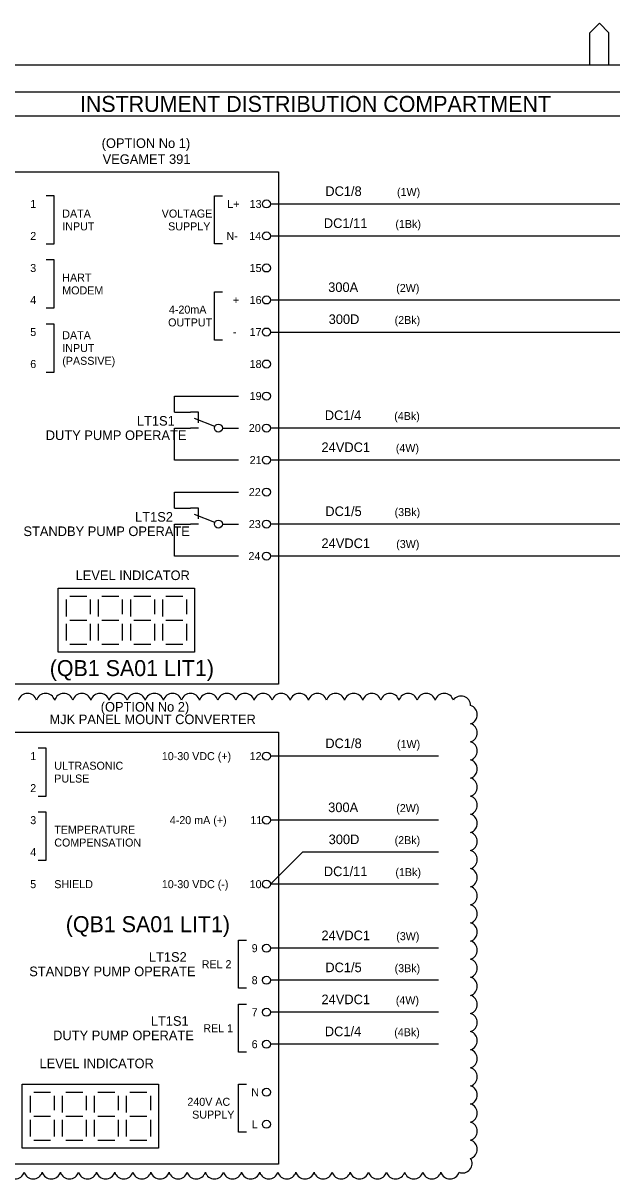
# Model space of a CAD drawing. Extents: x 0 to 841, y 0 to 594.
# Drawn here: x 240.3 to 424.1, y 232.9 to 594 of the extents above; entities that cross this region are included whole.
import ezdxf

# ---------------------------------------------------------------- set-up
doc = ezdxf.new("R2010")
doc.units = 0
for name, color, linetype in [('A1BORDER', 7, 'Continuous'), ('BASE', 7, 'Continuous'), ('Level 1', 7, 'Continuous'), ('Level 10', 7, 'Continuous'), ('Level 2', 7, 'Continuous')]:
    doc.layers.add(name, color=color, linetype=linetype)

msp = doc.modelspace()

# ---------------------------------------------------------------- linework, layer by layer
at = {"layer": 'A1BORDER'}
for p, q in [((417.19, 591), (420.19, 594)), ((423.19, 591), (420.19, 594)), ((417.19, 581), (417.19, 591)), ((423.19, 581), (423.19, 591)), ((28, 581), (829, 581))]:
    msp.add_line(p, q, dxfattribs=at)
at = {"layer": 'BASE'}
for p, q in [((317.5, 537.5), (602.5, 537.5)), ((317.5, 527.5), (602.5, 527.5)), ((317.5, 507.5), (602.5, 507.5)), ((317.5, 497.5), (602.5, 497.5))]:
    msp.add_line(p, q, dxfattribs=at)
at = {"layer": 'Level 1'}
for p, q in [((120, 572.5), (829, 572.5)), ((120, 565), (829, 565)), ((315, 537.5), (315, 537.5)), ((317.5, 537.5), (317.5, 537.5)), ((315, 527.5), (315, 527.5)), ((317.5, 527.5), (317.5, 527.5)), ((315, 517.5), (315, 517.5)), ((317.5, 517.5), (317.5, 517.5)), ((315, 507.5), (315, 507.5)), ((317.5, 507.5), (317.5, 507.5)), ((315, 497.5), (315, 497.5)), ((317.5, 497.5), (317.5, 497.5)), ((315, 487.5), (315, 487.5)), ((317.5, 487.5), (317.5, 487.5)), ((287.5, 472.5), (287.5, 477.5)), ((287.5, 477.5), (307.5, 477.5)), ((315, 477.5), (315, 477.5)), ((317.5, 477.5), (317.5, 477.5)), ((287.5, 472.5), (292.5, 472.5)), ((287.5, 457.5), (287.5, 467.5)), ((287.5, 467.5), (292.5, 467.5)), ((292.5, 467.5), (292.5, 467.5)), ((302.5, 467.5), (302.5, 467.5)), ((302.5, 467.5), (307.5, 467.5)), ((315, 467.5), (315, 467.5)), ((317.5, 467.5), (317.5, 467.5)), ((602.5, 467.5), (317.5, 467.5)), ((307.5, 457.5), (287.5, 457.5)), ((315, 457.5), (315, 457.5)), ((317.5, 457.5), (317.5, 457.5)), ((602.5, 457.5), (317.5, 457.5)), ((287.5, 442.5), (287.5, 447.5)), ((287.5, 447.5), (307.5, 447.5)), ((315, 447.5), (315, 447.5)), ((317.5, 447.5), (317.5, 447.5)), ((287.5, 442.5), (292.5, 442.5)), ((287.5, 427.5), (287.5, 437.5)), ((287.5, 437.5), (292.5, 437.5)), ((292.5, 437.5), (292.5, 437.5)), ((302.5, 437.5), (302.5, 437.5)), ((302.5, 437.5), (307.5, 437.5)), ((315, 437.5), (315, 437.5)), ((317.5, 437.5), (317.5, 437.5)), ((602.5, 437.5), (317.5, 437.5)), ((307.5, 427.5), (287.5, 427.5)), ((315, 427.5), (315, 427.5)), ((317.5, 427.5), (317.5, 427.5)), ((602.5, 427.5), (317.5, 427.5)), ((315, 365), (315, 365)), ((317.5, 365), (317.5, 365)), ((370, 365), (317.5, 365)), ((315, 345), (315, 345)), ((317.5, 345), (317.5, 345)), ((370, 345), (317.5, 345)), ((317.5, 325), (327.5, 335)), ((370, 335), (327.5, 335)), ((315, 325), (315, 325)), ((317.5, 325), (317.5, 325)), ((370, 325), (317.5, 325)), ((315, 305), (315, 305)), ((317.5, 305), (317.5, 305)), ((370, 305), (317.5, 305)), ((315, 295), (315, 295)), ((317.5, 295), (317.5, 295)), ((370, 295), (317.5, 295)), ((315, 285), (315, 285)), ((317.5, 285), (317.5, 285)), ((370, 285), (317.5, 285)), ((315, 275), (315, 275)), ((317.5, 275), (317.5, 275)), ((370, 275), (317.5, 275)), ((315, 260), (315, 260)), ((317.5, 260), (317.5, 260)), ((315, 250), (315, 250)), ((317.5, 250), (317.5, 250))]:
    msp.add_line(p, q, dxfattribs=at)
for points in [[(235, 387.5), (235, 547.5), (320, 547.5), (320, 387.5)], [(251.25, 417.5), (293.75, 417.5), (293.75, 397.5), (251.25, 397.5)], [(235, 237.5), (235, 372.5), (320, 372.5), (320, 237.5)], [(240, 262.5), (282.5, 262.5), (282.5, 242.5), (240, 242.5)]]:
    msp.add_lwpolyline(points, close=True, dxfattribs=at)
for points in [[(247.5, 525), (250, 525), (250, 540), (247.5, 540)], [(302.5, 525), (300, 525), (300, 540), (302.5, 540)], [(247.5, 505), (250, 505), (250, 520), (247.5, 520)], [(302.5, 495), (300, 495), (300, 510), (302.5, 510)], [(247.5, 485), (250, 485), (250, 500), (247.5, 500)], [(245, 352.5), (247.5, 352.5), (247.5, 367.5), (245, 367.5)], [(245, 332.5), (247.5, 332.5), (247.5, 347.5), (245, 347.5)], [(310, 292.5), (307.5, 292.5), (307.5, 307.5), (310, 307.5)], [(310, 272.5), (307.5, 272.5), (307.5, 287.5), (310, 287.5)], [(310, 247.5), (307.5, 247.5), (307.5, 262.5), (310, 262.5)]]:
    msp.add_lwpolyline(points, dxfattribs=at)
for centre, radius, start, end in [((241.64, 381.61), 2.97, 17.5, 162.5), ((247.3, 381.61), 2.97, 17.5, 162.5), ((252.96, 381.61), 2.97, 17.5, 162.5), ((258.62, 381.61), 2.97, 17.5, 162.5), ((264.28, 381.61), 2.97, 17.5, 162.5), ((269.93, 381.61), 2.97, 17.5, 162.5), ((275.59, 381.61), 2.97, 17.5, 162.5), ((281.25, 381.61), 2.97, 17.5, 162.5), ((286.91, 381.61), 2.97, 17.5, 162.5), ((292.56, 381.61), 2.97, 17.5, 162.5), ((298.22, 381.61), 2.97, 17.5, 162.5), ((303.88, 381.61), 2.97, 17.5, 162.5), ((309.54, 381.61), 2.97, 17.5, 162.5), ((315.2, 381.61), 2.97, 17.5, 162.5), ((320.85, 381.61), 2.97, 17.5, 162.5), ((326.51, 381.61), 2.97, 17.5, 162.5), ((332.17, 381.61), 2.97, 17.5, 162.5), ((337.83, 381.61), 2.97, 17.5, 162.5), ((343.48, 381.61), 2.97, 17.5, 162.5), ((349.14, 381.61), 2.97, 17.5, 162.5), ((354.8, 381.61), 2.97, 17.5, 162.5), ((360.46, 381.61), 2.97, 17.5, 162.5), ((366.12, 381.61), 2.97, 17.5, 162.5), ((371.77, 381.61), 2.97, 17.5, 162.5), ((377.03, 380.79), 2.97, 359.904, 144.904), ((379.11, 377.96), 2.97, 287.5, 72.5), ((379.11, 372.3), 2.97, 287.5, 72.5), ((379.11, 366.64), 2.97, 287.5, 72.5), ((379.11, 360.98), 2.97, 287.5, 72.5), ((379.11, 355.33), 2.97, 287.5, 72.5), ((379.11, 349.67), 2.97, 287.5, 72.5), ((379.11, 344.01), 2.97, 287.5, 72.5), ((379.11, 338.35), 2.97, 287.5, 72.5), ((379.11, 332.7), 2.97, 287.5, 72.5), ((379.11, 327.04), 2.97, 287.5, 72.5), ((379.11, 321.38), 2.97, 287.5, 72.5), ((379.11, 315.72), 2.97, 287.5, 72.5), ((379.11, 310.06), 2.97, 287.5, 72.5), ((379.11, 304.41), 2.97, 287.5, 72.5), ((379.11, 298.75), 2.97, 287.5, 72.5), ((379.11, 293.09), 2.97, 287.5, 72.5), ((379.11, 287.43), 2.97, 287.5, 72.5), ((379.11, 281.78), 2.97, 287.5, 72.5), ((379.11, 276.12), 2.97, 287.5, 72.5), ((379.11, 270.46), 2.97, 287.5, 72.5), ((379.11, 264.8), 2.97, 287.5, 72.5), ((379.11, 259.14), 2.97, 287.5, 72.5), ((379.11, 253.49), 2.97, 287.5, 72.5), ((379.11, 247.83), 2.97, 287.5, 72.5), ((379.11, 242.17), 2.97, 287.5, 72.5), ((377.5, 237.74), 2.96, 247.6624, 32.6624), ((237.76, 235.89), 2.97, 197.5, 342.5), ((243.42, 235.89), 2.97, 197.5, 342.5), ((249.08, 235.89), 2.97, 197.5, 342.5), ((254.73, 235.89), 2.97, 197.5, 342.5), ((260.39, 235.89), 2.97, 197.5, 342.5), ((266.05, 235.89), 2.97, 197.5, 342.5), ((271.71, 235.89), 2.97, 197.5, 342.5), ((277.36, 235.89), 2.97, 197.5, 342.5), ((283.02, 235.89), 2.97, 197.5, 342.5), ((288.68, 235.89), 2.97, 197.5, 342.5), ((294.34, 235.89), 2.97, 197.5, 342.5), ((300, 235.89), 2.97, 197.5, 342.5), ((305.65, 235.89), 2.97, 197.5, 342.5), ((311.31, 235.89), 2.97, 197.5, 342.5), ((316.97, 235.89), 2.97, 197.5, 342.5), ((322.63, 235.89), 2.97, 197.5, 342.5), ((328.28, 235.89), 2.97, 197.5, 342.5), ((333.94, 235.89), 2.97, 197.5, 342.5), ((339.6, 235.89), 2.97, 197.5, 342.5), ((345.26, 235.89), 2.97, 197.5, 342.5), ((350.92, 235.89), 2.97, 197.5, 342.5), ((356.57, 235.89), 2.97, 197.5, 342.5), ((362.23, 235.89), 2.97, 197.5, 342.5), ((367.89, 235.89), 2.97, 197.5, 342.5), ((373.55, 235.89), 2.97, 197.5, 342.5)]:
    msp.add_arc(centre, radius, start, end, dxfattribs=at)
at = {"layer": 'Level 10'}
for p, q in [((295, 472.5), (292.5, 472.5)), ((300.09, 467.96), (293.75, 470.5)), ((295, 469.13), (295, 472.5)), ((295, 467.5), (292.5, 467.5)), ((295, 442.5), (292.5, 442.5)), ((295, 439.13), (295, 442.5)), ((295, 437.5), (292.5, 437.5)), ((300.09, 437.96), (293.75, 440.5))]:
    msp.add_line(p, q, dxfattribs=at)
for centre in [(316.25, 537.5), (316.25, 527.5), (316.25, 517.5), (316.25, 507.5), (316.25, 497.5), (316.25, 487.5), (316.25, 477.5), (301.25, 467.5), (316.25, 467.5), (316.25, 457.5), (316.25, 447.5), (301.25, 437.5), (316.25, 437.5), (316.25, 427.5), (316.25, 365), (316.25, 345), (316.25, 325), (316.25, 305), (316.25, 295), (316.25, 285), (316.25, 275), (316.25, 260), (316.25, 250)]:
    msp.add_circle(centre, 1.25, dxfattribs=at)
at = {"layer": 'Level 2'}
for p, q in [((253.75, 413.88), (253.75, 408.63)), ((254.88, 415), (260.12, 415)), ((261.25, 413.88), (261.25, 409.38)), ((263.75, 413.88), (263.75, 408.63)), ((264.88, 415), (270.12, 415)), ((271.25, 413.88), (271.25, 409.38)), ((273.75, 413.88), (273.75, 408.63)), ((274.88, 415), (280.12, 415)), ((281.25, 413.88), (281.25, 409.38)), ((283.75, 413.88), (283.75, 408.63)), ((284.88, 415), (290.12, 415)), ((291.25, 413.88), (291.25, 409.38)), ((253.75, 406.38), (253.75, 401.13)), ((254.88, 407.5), (260.12, 407.5)), ((261.25, 406.38), (261.25, 401.13)), ((263.75, 406.38), (263.75, 401.13)), ((264.88, 407.5), (270.12, 407.5)), ((271.25, 406.38), (271.25, 401.13)), ((273.75, 406.38), (273.75, 401.13)), ((274.88, 407.5), (280.12, 407.5)), ((281.25, 406.38), (281.25, 401.13)), ((283.75, 406.38), (283.75, 401.13)), ((284.88, 407.5), (290.12, 407.5)), ((291.25, 406.38), (291.25, 401.13)), ((254.88, 400), (260.12, 400)), ((264.88, 400), (270.12, 400)), ((274.88, 400), (280.12, 400)), ((284.88, 400), (290.12, 400)), ((243.63, 260), (248.87, 260)), ((253.63, 260), (258.87, 260)), ((263.63, 260), (268.87, 260)), ((273.63, 260), (278.87, 260)), ((242.5, 258.88), (242.5, 253.63)), ((250, 258.88), (250, 254.38)), ((252.5, 258.88), (252.5, 253.63)), ((260, 258.88), (260, 254.38)), ((262.5, 258.88), (262.5, 253.63)), ((270, 258.88), (270, 254.38)), ((272.5, 258.88), (272.5, 253.63)), ((280, 258.88), (280, 254.38)), ((242.5, 251.38), (242.5, 246.13)), ((243.63, 252.5), (248.87, 252.5)), ((250, 251.38), (250, 246.13)), ((252.5, 251.38), (252.5, 246.13)), ((253.63, 252.5), (258.87, 252.5)), ((260, 251.38), (260, 246.13)), ((262.5, 251.38), (262.5, 246.13)), ((263.63, 252.5), (268.87, 252.5)), ((270, 251.38), (270, 246.13)), ((272.5, 251.38), (272.5, 246.13)), ((273.63, 252.5), (278.87, 252.5)), ((280, 251.38), (280, 246.13)), ((243.63, 245), (248.87, 245)), ((253.63, 245), (258.87, 245)), ((263.63, 245), (268.87, 245)), ((273.63, 245), (278.87, 245))]:
    msp.add_line(p, q, dxfattribs=at)

# ---------------------------------------------------------------- texts
at = {"layer": 'Level 1'}
for s, height, p in [('INSTRUMENT DISTRIBUTION COMPARTMENT', 5, (258, 566.25)), ('(OPTION No 1)', 3, (264.8, 555)), ('VEGAMET 391', 3, (265.1, 550)), ('DC1/8', 3, (334.62, 540)), ('(1W)', 2.5, (357.01, 540)), ('1', 2.5, (242.5, 536.25)), ('L+', 2.5, (304.01, 536.25)), ('13', 2.5, (311, 536.25)), ('DATA', 2.5, (252.5, 533.25)), ('VOLTAGE', 2.5, (283.55, 533.25)), ('INPUT', 2.5, (252.5, 529.25)), ('SUPPLY', 2.5, (285.55, 529.25)), ('DC1/11', 3, (334.17, 530)), ('(1Bk)', 2.5, (356.51, 530)), ('2', 2.5, (242.5, 526.25)), ('N-', 2.5, (303.76, 526.25)), ('14', 2.5, (310.88, 526.25)), ('3', 2.5, (242.5, 516.25)), ('15', 2.5, (311, 516.25)), ('HART', 2.5, (252.5, 513.25)), ('300A', 3, (335.52, 510)), ('MODEM', 2.5, (252.5, 509.25)), ('(2W)', 2.5, (356.76, 510)), ('4', 2.5, (242.5, 506.25)), ('4-20mA', 2.5, (285.79, 503.25)), ('+', 2.5, (305.76, 506.25)), ('16', 2.5, (311, 506.25)), ('300D', 3, (335.67, 500)), ('(2Bk)', 2.5, (356.26, 500)), ('5', 2.5, (242.5, 496.25)), ('OUTPUT', 2.5, (285.55, 499.25)), ('17', 2.5, (311, 496.25)), ('DATA', 2.5, (252.5, 495.25)), ('-', 2.5, (305.76, 496.25)), ('INPUT', 2.5, (252.5, 491.25)), ('6', 2.5, (242.5, 486.25)), ('(PASSIVE)', 2.5, (252.5, 487.25)), ('18', 2.5, (311, 486.25)), ('19', 2.5, (311, 476.25)), ('DC1/4', 3, (334.47, 470)), ('LT1S1', 3, (275.8, 468.25)), ('(4Bk)', 2.5, (356.14, 470)), ('DUTY PUMP OPERATE', 3, (247.35, 463.75)), ('20', 2.5, (310.75, 466.25)), ('24VDC1', 3, (333.43, 460)), ('(4W)', 2.5, (356.64, 460)), ('21', 2.5, (311, 456.25)), ('22', 2.5, (310.75, 446.25)), ('LT1S2', 3, (275.24, 438.25)), ('DC1/5', 3, (334.62, 440)), ('(3Bk)', 2.5, (356.26, 440)), ('23', 2.5, (310.75, 436.25)), ('STANDBY PUMP OPERATE', 3, (240.38, 433.75)), ('24VDC1', 3, (333.43, 430)), ('(3W)', 2.5, (356.76, 430)), ('24', 2.5, (310.63, 426.25)), ('(QB1 SA01 LIT1)', 5, (248.59, 390)), ('(OPTION No 2)', 3, (264.5, 378.9)), ('MJK PANEL MOUNT CONVERTER', 3, (248.51, 375)), ('DC1/8', 3, (334.62, 367.5)), ('(1W)', 2.5, (357.01, 367.5)), ('1', 2.5, (242.5, 363.75)), ('10-30 VDC (+)', 2.5, (283.58, 363.75)), ('12', 2.5, (311, 363.75)), ('ULTRASONIC', 2.5, (250, 360.75)), ('PULSE', 2.5, (250, 356.75)), ('2', 2.5, (242.5, 353.75)), ('300A', 3, (335.52, 347.5)), ('(2W)', 2.5, (356.76, 347.5)), ('3', 2.5, (242.5, 343.75)), ('TEMPERATURE', 2.5, (250, 340.75)), ('4-20 mA (+)', 2.5, (286.07, 343.75)), ('11', 2.5, (311.25, 343.75)), ('300D', 3, (335.67, 337.5)), ('(2Bk)', 2.5, (356.26, 337.5)), ('4', 2.5, (242.5, 333.75)), ('COMPENSATION', 2.5, (250, 336.75)), ('DC1/11', 3, (334.17, 327.5)), ('(1Bk)', 2.5, (356.51, 327.5)), ('5', 2.5, (242.5, 323.75)), ('SHIELD', 2.5, (250, 323.75)), ('10-30 VDC (-)', 2.5, (283.58, 323.75)), ('10', 2.5, (311, 323.75)), ('(QB1 SA01 LIT1)', 5, (253.59, 310)), ('24VDC1', 3, (333.43, 307.5)), ('(3W)', 2.5, (356.76, 307.5)), ('LT1S2', 3, (279.54, 300.75)), ('9', 2.5, (311.63, 303.75)), ('REL 2', 2.5, (296.03, 298.75)), ('DC1/5', 3, (334.62, 297.5)), ('(3Bk)', 2.5, (356.26, 297.5)), ('STANDBY PUMP OPERATE', 3, (242.19, 296.25)), ('8', 2.5, (311.63, 293.75)), ('24VDC1', 3, (333.43, 287.5)), ('(4W)', 2.5, (356.64, 287.5)), ('7', 2.5, (311.63, 283.75)), ('LT1S1', 3, (280.14, 280.75)), ('DUTY PUMP OPERATE', 3, (249.66, 276.25)), ('REL 1', 2.5, (296.53, 278.75)), ('DC1/4', 3, (334.47, 277.5)), ('(4Bk)', 2.5, (356.14, 277.5)), ('6', 2.5, (311.63, 273.75)), ('N', 2.5, (311.5, 258.75)), ('240V AC', 2.5, (291.55, 255.75)), ('SUPPLY', 2.5, (293.05, 251.75)), ('L', 2.5, (311.63, 248.75))]:
    msp.add_text(s, height=height, dxfattribs=at).set_placement(p)
at = {"layer": 'Level 2'}
for p in [(256.66, 420), (245.41, 267.5)]:
    msp.add_text('LEVEL INDICATOR', height=3, dxfattribs=at).set_placement(p)

doc.saveas('drawing.dxf')
